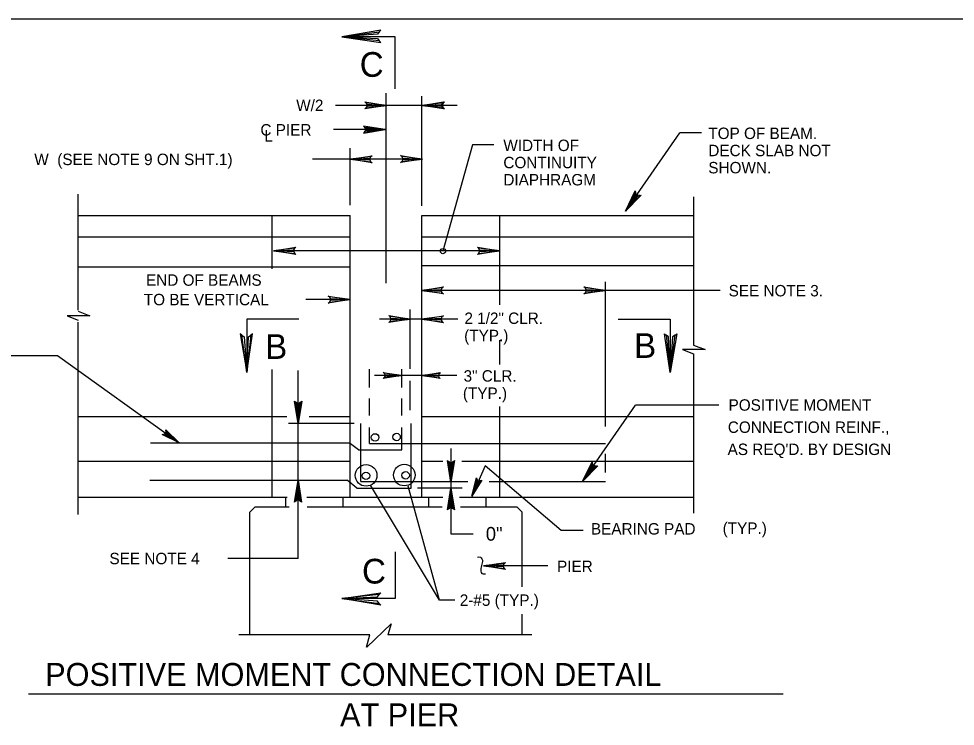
# Model space of a CAD drawing. Extents: x 639980 to 641204, y 298038 to 300414.
# Drawn here: x 640279.6 to 640524.8, y 299619.4 to 299804.8 of the extents above; entities that cross this region are included whole.
import ezdxf

# ---------------------------------------------------------------- set-up
doc = ezdxf.new("R2010")
doc.units = 0
for name, color, linetype in [('1', 7, 'Continuous'), ('2', 7, 'Continuous'), ('3', 7, 'Continuous')]:
    doc.layers.add(name, color=color, linetype=linetype)

msp = doc.modelspace()

# ---------------------------------------------------------------- linework, layer by layer
at = {"layer": '1'}
for p, q in [((640375.75, 299735.5), (640375.75, 299785.23)), ((640345.97, 299739.25), (640345.97, 299753.25)), ((640366.37, 299679.42), (640366.37, 299753.25)), ((640385.12, 299679.42), (640385.12, 299753.25)), ((640405.52, 299729.77), (640405.52, 299753.25)), ((640405.52, 299714.2), (640405.52, 299720.52)), ((640345.97, 299679.42), (640345.97, 299712.85)), ((640405.52, 299679.42), (640405.52, 299703.14)), ((640368.57, 299691.78), (640366.13, 299693.67)), ((640368.13, 299681.78), (640365.56, 299683.89))]:
    msp.add_line(p, q, dxfattribs=at)
msp.add_spline([(640399.69, 299663.7), (640400.46, 299663.64), (640400.88, 299663.24), (640401.05, 299662.51), (640400.84, 299661.82), (640400.69, 299661.09), (640400.57, 299660.36), (640400.65, 299659.63), (640401.19, 299659.32), (640401.78, 299659.32)], degree=3, dxfattribs=at)
at = {"layer": '2'}
for p, q in [((640020.31, 299804.78), (640806.31, 299804.78)), ((640378.17, 299800.05), (640364.22, 299800.05)), ((640378.17, 299786.42), (640378.17, 299800.05)), ((640385.12, 299755.74), (640385.12, 299784.49)), ((640375.94, 299782.07), (640362.56, 299782.07)), ((640385.17, 299782.07), (640375.94, 299782.07)), ((640394.37, 299782.07), (640385.12, 299782.07)), ((640375.55, 299775.75), (640361.97, 299775.75)), ((640458.36, 299774.84), (640452.69, 299774.84)), ((640366.37, 299755.94), (640366.37, 299770.83)), ((640398.39, 299771.69), (640390.67, 299743.88)), ((640403.98, 299771.69), (640398.39, 299771.69)), ((640366.37, 299767.97), (640356.49, 299767.97)), ((640385.31, 299767.97), (640366.37, 299767.97)), ((640295.12, 299728.42), (640295.12, 299758.83)), ((640456.37, 299719.27), (640456.37, 299758.09)), ((640295.12, 299753.25), (640366.37, 299753.25)), ((640385.12, 299753.25), (640456.37, 299753.25)), ((640295.12, 299747.63), (640366.37, 299747.63)), ((640385.12, 299747.63), (640456.37, 299747.63)), ((640405.52, 299743.95), (640346.33, 299743.95)), ((640295.12, 299739.78), (640366.37, 299739.78)), ((640385.12, 299740.13), (640456.37, 299740.13)), ((640463.27, 299733.56), (640385.12, 299733.56)), ((640366.37, 299731.18), (640354.76, 299731.18)), ((640298.18, 299726.92), (640292.25, 299726.92)), ((640292.25, 299726.92), (640295.17, 299725.78)), ((640295.17, 299728.1), (640298.18, 299726.92)), ((640382.12, 299713.01), (640382.12, 299728.59)), ((640295.12, 299674.87), (640295.12, 299725.26)), ((640352.9, 299726.04), (640339.27, 299726.04)), ((640339.27, 299726.04), (640339.27, 299712.09)), ((640394.59, 299726.05), (640374.07, 299726.05)), ((640436.53, 299726.04), (640450.16, 299726.04)), ((640450.16, 299726.04), (640450.16, 299712.09)), ((640459.34, 299718.09), (640453.4, 299718.09)), ((640453.4, 299718.09), (640456.32, 299716.95)), ((640456.32, 299719.27), (640459.34, 299718.09)), ((640456.37, 299675.21), (640456.37, 299716.95)), ((640262.77, 299716.48), (640289.71, 299716.48)), ((640289.71, 299716.48), (640321.59, 299693.67)), ((640371.44, 299708.17), (640371.44, 299712.96)), ((640379.9, 299708.17), (640379.9, 299712.96)), ((640379.9, 299711.27), (640372.72, 299711.27)), ((640385.12, 299711.27), (640379.9, 299711.27)), ((640382.12, 299702.23), (640382.12, 299709.86)), ((640394.34, 299711.27), (640385.12, 299711.27)), ((640371.44, 299700.83), (640371.44, 299705.27)), ((640379.9, 299700.83), (640379.9, 299705.27)), ((640462.87, 299703.53), (640441.09, 299703.53)), ((640295.12, 299700.52), (640349.79, 299700.52)), ((640355.66, 299700.52), (640366.37, 299700.52)), ((640385.12, 299700.52), (640456.37, 299700.52)), ((640367.38, 299698.74), (640350.24, 299698.74)), ((640369.18, 299683.47), (640369.18, 299698.74)), ((640371.44, 299693.47), (640371.44, 299697.68)), ((640379.9, 299691.78), (640379.9, 299697.68)), ((640382.31, 299681.78), (640382.31, 299698.74)), ((640314.11, 299693.67), (640366.13, 299693.67)), ((640371.44, 299693.47), (640433.2, 299693.47)), ((640368.57, 299691.78), (640379.9, 299691.78)), ((640295.12, 299688.8), (640366.37, 299688.8)), ((640385.12, 299688.8), (640390.62, 299688.8)), ((640395.58, 299688.8), (640456.37, 299688.8)), ((640421.64, 299670.67), (640401.7, 299687.63)), ((640313.88, 299683.89), (640365.56, 299683.89)), ((640369.18, 299683.47), (640397.16, 299683.47)), ((640402.79, 299683.47), (640433.2, 299683.47)), ((640368.13, 299681.78), (640382.31, 299681.78)), ((640395.69, 299681.78), (640383.96, 299681.78)), ((640295.12, 299679.42), (640349.9, 299679.42)), ((640349.5, 299676.89), (640349.5, 299679.42)), ((640354.98, 299679.42), (640385.12, 299679.42)), ((640364.5, 299676.89), (640364.5, 299679.42)), ((640385.12, 299679.42), (640390.62, 299679.42)), ((640387, 299676.89), (640387, 299679.42)), ((640395.01, 299679.42), (640456.37, 299679.42)), ((640401.99, 299676.89), (640401.99, 299679.42)), ((640340.12, 299675.48), (640341.53, 299676.89)), ((640340.12, 299643.31), (640340.12, 299675.48)), ((640341.53, 299676.89), (640350.36, 299676.89)), ((640355.09, 299676.89), (640390.5, 299676.89)), ((640395.24, 299676.89), (640409.97, 299676.89)), ((640411.37, 299675.48), (640409.97, 299676.89)), ((640411.37, 299655.88), (640411.37, 299675.48)), ((640427.38, 299670.67), (640421.64, 299670.67)), ((640352.74, 299663.35), (640334.29, 299663.35)), ((640378.17, 299665.06), (640378.17, 299652.83)), ((640418.09, 299661.4), (640401.3, 299661.4)), ((640378.17, 299652.83), (640364.22, 299652.83)), ((640393.75, 299652.38), (640389.72, 299652.38)), ((640411.37, 299643.31), (640411.37, 299648.74)), ((640370.69, 299640.09), (640377.06, 299646.24)), ((640377.06, 299646.24), (640376.22, 299643.31)), ((640371.55, 299643.31), (640337.19, 299643.31)), ((640370.67, 299640.09), (640371.53, 299643.31)), ((640413.91, 299643.31), (640376.22, 299643.31)), ((640282.14, 299627.88), (640479.76, 299627.88))]:
    msp.add_line(p, q, dxfattribs=at)
for points in [[(640373.94, 299801.34), (640373.51, 299800.7), (640364.22, 299800.05), (640373.94, 299801.34), (640374.37, 299801.78), (640364.22, 299800.05), (640373.51, 299799.62), (640373.94, 299798.97), (640364.22, 299800.05), (640374.37, 299798.54), (640373.94, 299798.97)], [(640442.19, 299758.48), (640441.74, 299758.54), (640438.46, 299754.33), (640442.19, 299758.48), (640442.55, 299758.58), (640438.46, 299754.33), (640441.28, 299758.86), (640441.07, 299759.24), (640438.46, 299754.33), (640441.02, 299759.64), (640441.07, 299759.24)], [(640351.86, 299743.25), (640351.66, 299743.65), (640346.33, 299743.95), (640351.86, 299743.25), (640352.15, 299743.01), (640346.33, 299743.95), (640351.65, 299744.21), (640351.85, 299744.61), (640346.33, 299743.95), (640352.15, 299744.87), (640351.85, 299744.61)], [(640399.98, 299744.64), (640400.19, 299744.24), (640405.52, 299743.95), (640399.98, 299744.64), (640399.7, 299744.88), (640405.52, 299743.95), (640400.19, 299743.68), (640400, 299743.29), (640405.52, 299743.95), (640399.7, 299743.02), (640400, 299743.29)], [(640337.97, 299721.81), (640338.62, 299721.38), (640339.27, 299712.09), (640337.97, 299721.81), (640337.54, 299722.24), (640339.27, 299712.09), (640339.7, 299721.38), (640340.35, 299721.81), (640339.27, 299712.09), (640340.78, 299722.24), (640340.35, 299721.81)], [(640451.45, 299721.81), (640450.81, 299721.38), (640450.16, 299712.09), (640451.45, 299721.81), (640451.89, 299722.24), (640450.16, 299712.09), (640449.73, 299721.38), (640449.08, 299721.81), (640450.16, 299712.09), (640448.65, 299722.24), (640449.08, 299721.81)], [(640375.29, 299711.85), (640375.46, 299711.52), (640379.9, 299711.27), (640375.29, 299711.85), (640375.05, 299712.05), (640379.9, 299711.27), (640375.46, 299711.05), (640375.3, 299710.72), (640379.9, 299711.27), (640375.05, 299710.5), (640375.3, 299710.72)], [(640389.74, 299710.69), (640389.56, 299711.03), (640385.12, 299711.27), (640389.74, 299710.69), (640389.97, 299710.49), (640385.12, 299711.27), (640389.56, 299711.49), (640389.72, 299711.82), (640385.12, 299711.27), (640389.97, 299712.04), (640389.72, 299711.82)], [(640353.43, 299704.28), (640353.03, 299704.07), (640352.74, 299698.74), (640353.43, 299704.28), (640353.67, 299704.56), (640352.74, 299698.74), (640352.47, 299704.07), (640352.08, 299704.26), (640352.74, 299698.74), (640351.81, 299704.56), (640352.08, 299704.26)], [(640318.13, 299696.77), (640318.08, 299696.4), (640321.59, 299693.67), (640318.13, 299696.77), (640318.05, 299697.07), (640321.59, 299693.67), (640317.82, 299696.02), (640317.5, 299695.84), (640321.59, 299693.67), (640317.17, 299695.8), (640317.5, 299695.84)], [(640352.04, 299678.36), (640352.44, 299678.56), (640352.74, 299683.89), (640352.04, 299678.36), (640351.8, 299678.07), (640352.74, 299683.89), (640353, 299678.57), (640353.4, 299678.37), (640352.74, 299683.89), (640353.66, 299678.07), (640353.4, 299678.37)], [(640400.6, 299683.69), (640400.22, 299683.66), (640398.21, 299679.7), (640400.6, 299683.69), (640400.88, 299683.82), (640398.21, 299679.7), (640399.8, 299683.85), (640399.56, 299684.13), (640398.21, 299679.7), (640399.46, 299684.45), (640399.56, 299684.13)], [(640373.94, 299651.53), (640373.51, 299652.18), (640364.22, 299652.83), (640373.94, 299651.53), (640374.37, 299651.1), (640364.22, 299652.83), (640373.51, 299653.26), (640373.94, 299653.91), (640364.22, 299652.83), (640374.37, 299654.34), (640373.94, 299653.91)]]:
    msp.add_lwpolyline(points, dxfattribs=at)
for centre, radius in [((640390.67, 299743.88), 0.679), ((640372.88, 299695.05), 0.977), ((640378.52, 299695.16), 0.977), ((640370.53, 299685.11), 2.84), ((640380.55, 299685.2), 2.84), ((640370.51, 299685), 0.977), ((640380.89, 299685.12), 0.977)]:
    msp.add_circle(centre, radius, dxfattribs=at)
at = {"layer": '3'}
for p, q in [((640438.46, 299754.33), (640452.69, 299774.84)), ((640307.96, 299753.25), (640307.96, 299753.25)), ((640433.25, 299697.95), (640433.25, 299735.81)), ((640352.74, 299698.74), (640352.74, 299712.56)), ((640427.19, 299683.47), (640441.09, 299703.53)), ((640352.74, 299683.89), (640352.74, 299698.74)), ((640392.76, 299692.19), (640392.76, 299683.47)), ((640433.25, 299685.86), (640433.25, 299690.76)), ((640401.7, 299687.63), (640398.21, 299679.7)), ((640352.74, 299663.35), (640352.74, 299683.89)), ((640392.76, 299683.47), (640392.76, 299681.79)), ((640392.76, 299683.3), (640392.76, 299683.3)), ((640389.72, 299652.38), (640371.69, 299682.52)), ((640389.72, 299652.38), (640381.59, 299682.27)), ((640392.76, 299681.79), (640392.76, 299681.79)), ((640392.76, 299681.79), (640392.76, 299669.78)), ((640392.76, 299669.78), (640398.54, 299669.78))]:
    msp.add_line(p, q, dxfattribs=at)
for points in [[(640370.49, 299782.76), (640370.69, 299782.36), (640375.94, 299782.07), (640370.49, 299782.76), (640370.21, 299783), (640375.94, 299782.07), (640370.7, 299781.81), (640370.51, 299781.42), (640375.94, 299782.07), (640370.21, 299781.16), (640370.51, 299781.42)], [(640370.49, 299782.76), (640370.69, 299782.36), (640375.94, 299782.07), (640370.49, 299782.76), (640370.21, 299783), (640375.94, 299782.07), (640370.7, 299781.81), (640370.51, 299781.42), (640375.94, 299782.07), (640370.21, 299781.16), (640370.51, 299781.42)], [(640390.57, 299781.39), (640390.37, 299781.78), (640385.12, 299782.07), (640390.57, 299781.39), (640390.85, 299781.15), (640385.12, 299782.07), (640390.36, 299782.33), (640390.55, 299782.72), (640385.12, 299782.07), (640390.85, 299782.98), (640390.55, 299782.72)], [(640390.83, 299781.39), (640390.63, 299781.78), (640385.38, 299782.07), (640390.83, 299781.39), (640391.11, 299781.15), (640385.38, 299782.07), (640390.62, 299782.33), (640390.81, 299782.72), (640385.38, 299782.07), (640391.11, 299782.98), (640390.81, 299782.72)], [(640370.1, 299775.07), (640370.3, 299775.46), (640375.55, 299775.75), (640370.1, 299775.07), (640369.82, 299774.83), (640375.55, 299775.75), (640370.31, 299776.01), (640370.12, 299776.4), (640375.55, 299775.75), (640369.82, 299776.66), (640370.12, 299776.4)], [(640371.82, 299767.29), (640371.62, 299767.68), (640366.37, 299767.97), (640371.82, 299767.29), (640372.1, 299767.05), (640366.37, 299767.97), (640371.61, 299768.23), (640371.8, 299768.62), (640366.37, 299767.97), (640372.1, 299768.88), (640371.8, 299768.62)], [(640379.86, 299768.66), (640380.07, 299768.26), (640385.31, 299767.97), (640379.86, 299768.66), (640379.58, 299768.9), (640385.31, 299767.97), (640380.07, 299767.71), (640379.88, 299767.32), (640385.31, 299767.97), (640379.58, 299767.06), (640379.88, 299767.32)], [(640390.52, 299732.89), (640390.32, 299733.29), (640385.07, 299733.58), (640390.52, 299732.89), (640390.8, 299732.66), (640385.07, 299733.58), (640390.31, 299733.84), (640390.5, 299734.23), (640385.07, 299733.58), (640390.8, 299734.49), (640390.5, 299734.23)], [(640427.87, 299734.24), (640428.08, 299733.85), (640433.32, 299733.56), (640427.87, 299734.24), (640427.59, 299734.48), (640433.32, 299733.56), (640428.08, 299733.3), (640427.89, 299732.91), (640433.32, 299733.56), (640427.59, 299732.65), (640427.89, 299732.91)], [(640360.92, 299731.87), (640361.13, 299731.47), (640366.37, 299731.18), (640360.92, 299731.87), (640360.64, 299732.11), (640366.37, 299731.18), (640361.13, 299730.92), (640360.94, 299730.53), (640366.37, 299731.18), (640360.64, 299730.27), (640360.94, 299730.53)], [(640376.72, 299726.74), (640376.93, 299726.34), (640382.17, 299726.05), (640376.72, 299726.74), (640376.45, 299726.98), (640382.17, 299726.05), (640376.93, 299725.79), (640376.74, 299725.4), (640382.17, 299726.05), (640376.45, 299725.14), (640376.74, 299725.4)], [(640390.52, 299725.36), (640390.31, 299725.76), (640385.07, 299726.05), (640390.52, 299725.36), (640390.79, 299725.12), (640385.07, 299726.05), (640390.31, 299726.31), (640390.5, 299726.7), (640385.07, 299726.05), (640390.79, 299726.96), (640390.5, 299726.7)], [(640393.45, 299688.75), (640393.05, 299688.54), (640392.76, 299683.3), (640393.45, 299688.75), (640393.69, 299689.03), (640392.76, 299683.3), (640392.5, 299688.54), (640392.11, 299688.73), (640392.76, 299683.3), (640391.85, 299689.03), (640392.11, 299688.73)], [(640393.45, 299688.75), (640393.05, 299688.54), (640392.76, 299683.3), (640393.45, 299688.75), (640393.69, 299689.03), (640392.76, 299683.3), (640392.5, 299688.54), (640392.11, 299688.73), (640392.76, 299683.3), (640391.85, 299689.03), (640392.11, 299688.73)], [(640430.85, 299687.55), (640430.41, 299687.61), (640427.19, 299683.47), (640430.85, 299687.55), (640431.21, 299687.65), (640427.19, 299683.47), (640429.96, 299687.92), (640429.75, 299688.3), (640427.19, 299683.47), (640429.7, 299688.69), (640429.75, 299688.3)], [(640392.08, 299676.34), (640392.47, 299676.55), (640392.76, 299681.79), (640392.08, 299676.34), (640391.84, 299676.07), (640392.76, 299681.79), (640393.02, 299676.55), (640393.41, 299676.36), (640392.76, 299681.79), (640393.67, 299676.07), (640393.41, 299676.36)], [(640406.75, 299660.72), (640406.55, 299661.11), (640401.3, 299661.4), (640406.75, 299660.72), (640407.03, 299660.48), (640401.3, 299661.4), (640406.55, 299661.66), (640406.74, 299662.05), (640401.3, 299661.4), (640407.03, 299662.31), (640406.74, 299662.05)], [(640404.94, 299660.95), (640404.8, 299661.21), (640401.3, 299661.4), (640404.94, 299660.95), (640405.12, 299660.79), (640401.3, 299661.4), (640404.8, 299661.58), (640404.93, 299661.84), (640401.3, 299661.4), (640405.12, 299662.01), (640404.93, 299661.84)]]:
    msp.add_lwpolyline(points, dxfattribs=at)

# ---------------------------------------------------------------- texts
at = {"layer": '2'}
for s, height, p in [('C', 6.48, (640368.87, 299789.55)), ('W  (SEE NOTE 9 ON SHT.1)', 3, (640283.64, 299766.42)), ('B', 6.48, (640344.1, 299715.63)), ('B', 6.48, (640440.72, 299715.89)), ('SEE NOTE 4', 3, (640303.32, 299661.82)), ('C', 6.48, (640369.47, 299656.76)), ('POSITIVE MOMENT CONNECTION DETAIL', 6, (640286.5, 299629.94)), ('AT PIER', 6, (640363.72, 299619.35))]:
    msp.add_text(s, height=height, dxfattribs=at).set_placement(p)
at = {"layer": '3'}
for s, height, p in [('W/2', 2.997, (640352.24, 299780.59)), ('C PIER', 2.997, (640342.86, 299774.17)), ('TOP OF BEAM.', 2.9969, (640460.16, 299773.25)), ('L', 3, (640343.87, 299772.6)), ('WIDTH OF', 2.997, (640406.48, 299770.09)), ('DECK SLAB NOT', 2.9969, (640460.16, 299768.75)), ('CONTINUITY', 2.997, (640406.48, 299765.59)), ('SHOWN.', 2.997, (640460.16, 299764.25)), ('DIAPHRAGM', 2.997, (640406.48, 299761.09)), ('END OF BEAMS', 2.9968, (640312.9, 299734.8)), ('SEE NOTE 3.', 2.9957, (640465.48, 299732.01)), ('TO BE VERTICAL', 2.9968, (640312.32, 299729.68)), ('2 1/2" CLR.', 2.9968, (640396.29, 299724.79)), ('(TYP.)', 2.997, (640396.22, 299720.26)), ('3" CLR.', 2.997, (640396.07, 299709.67)), ('(TYP.)', 2.997, (640395.88, 299705.14)), ('POSITIVE MOMENT', 2.9968, (640465.46, 299702.05)), ('CONNECTION REINF.,', 2.9968, (640465.27, 299696.24)), ("AS REQ'D. BY DESIGN", 2.9968, (640465.21, 299690.44)), ('(TYP.)', 2.997, (640463.91, 299669.78)), ('0"', 3.595, (640401.89, 299667.99)), ('BEARING PAD', 2.9968, (640429.42, 299669.6)), ('PIER', 2.997, (640420.54, 299659.76)), ('2-#5 (TYP.)', 2.9968, (640395.07, 299650.91))]:
    msp.add_text(s, height=height, dxfattribs=at).set_placement(p)

doc.saveas('drawing.dxf')
